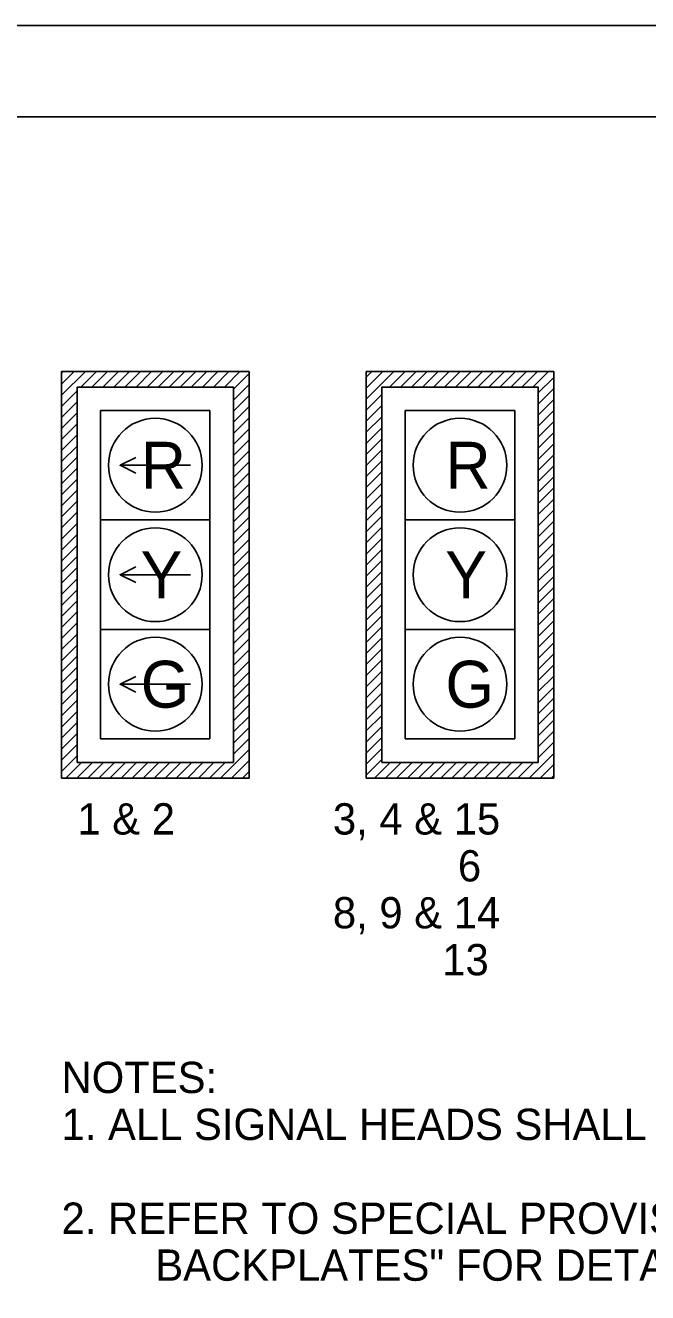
# Model space of a CAD drawing. Extents: x 1710114 to 1711114, y 557211 to 557851.
# Drawn here: x 1710304.6 to 1710384.3, y 557689.1 to 557851.1 of the extents above; entities that cross this region are included whole.
import ezdxf

# ---------------------------------------------------------------- set-up
doc = ezdxf.new("R2010")
doc.units = 0
for name, color, linetype in [('E_Existing ROW', 7, 'Continuous'), ('R_Alt Surface', 7, 'Continuous'), ('R_Alt Surface Annot', 7, 'Continuous'), ('R_Dimension', 7, 'Continuous')]:
    doc.layers.add(name, color=color, linetype=linetype)

msp = doc.modelspace()

# ---------------------------------------------------------------- linework, layer by layer
at = {"layer": 'E_Existing ROW'}
for p, q in [((1710309.23, 557806.9), (1710333.23, 557806.9)), ((1710309.23, 557754.9), (1710309.23, 557806.9)), ((1710309.23, 557803.85), (1710312.28, 557806.9)), ((1710309.23, 557805.26), (1710310.86, 557806.9)), ((1710309.23, 557806.68), (1710309.45, 557806.9)), ((1710311.69, 557804.9), (1710313.69, 557806.9)), ((1710313.1, 557804.9), (1710315.1, 557806.9)), ((1710314.52, 557804.9), (1710316.52, 557806.9)), ((1710315.93, 557804.9), (1710317.93, 557806.9)), ((1710317.35, 557804.9), (1710319.35, 557806.9)), ((1710318.76, 557804.9), (1710320.76, 557806.9)), ((1710320.18, 557804.9), (1710322.18, 557806.9)), ((1710321.59, 557804.9), (1710323.59, 557806.9)), ((1710323, 557804.9), (1710325, 557806.9)), ((1710324.42, 557804.9), (1710326.42, 557806.9)), ((1710325.83, 557804.9), (1710327.83, 557806.9)), ((1710327.25, 557804.9), (1710329.25, 557806.9)), ((1710328.66, 557804.9), (1710330.66, 557806.9)), ((1710330.07, 557804.9), (1710332.07, 557806.9)), ((1710331.23, 557804.63), (1710333.23, 557806.63)), ((1710333.23, 557806.9), (1710333.23, 557754.9)), ((1710372.23, 557806.9), (1710348.23, 557806.9)), ((1710348.23, 557806.9), (1710348.23, 557754.9)), ((1710348.23, 557803.35), (1710351.77, 557806.9)), ((1710348.23, 557804.76), (1710350.36, 557806.9)), ((1710348.23, 557806.18), (1710348.94, 557806.9)), ((1710351.19, 557804.9), (1710353.19, 557806.9)), ((1710352.6, 557804.9), (1710354.6, 557806.9)), ((1710354.02, 557804.9), (1710356.02, 557806.9)), ((1710355.43, 557804.9), (1710357.43, 557806.9)), ((1710356.84, 557804.9), (1710358.84, 557806.9)), ((1710358.26, 557804.9), (1710360.26, 557806.9)), ((1710359.67, 557804.9), (1710361.67, 557806.9)), ((1710361.09, 557804.9), (1710363.09, 557806.9)), ((1710362.5, 557804.9), (1710364.5, 557806.9)), ((1710363.91, 557804.9), (1710365.91, 557806.9)), ((1710365.33, 557804.9), (1710367.33, 557806.9)), ((1710366.74, 557804.9), (1710368.74, 557806.9)), ((1710368.16, 557804.9), (1710370.16, 557806.9)), ((1710369.57, 557804.9), (1710371.57, 557806.9)), ((1710372.23, 557754.9), (1710372.23, 557806.9)), ((1710331.23, 557803.22), (1710333.23, 557805.22)), ((1710370.23, 557804.14), (1710372.23, 557806.14)), ((1710309.23, 557802.43), (1710311.23, 557804.43)), ((1710331.23, 557801.81), (1710333.23, 557803.81)), ((1710348.23, 557801.94), (1710350.23, 557803.94)), ((1710370.23, 557802.72), (1710372.23, 557804.72)), ((1710370.23, 557801.31), (1710372.23, 557803.31)), ((1710309.23, 557801.02), (1710311.23, 557803.02)), ((1710309.23, 557799.6), (1710311.23, 557801.6)), ((1710314.23, 557801.9), (1710328.23, 557801.9)), ((1710314.23, 557801.9), (1710314.23, 557787.9)), ((1710328.23, 557801.9), (1710328.23, 557787.9)), ((1710331.23, 557800.39), (1710333.23, 557802.39)), ((1710348.23, 557800.52), (1710350.23, 557802.52)), ((1710353.23, 557801.9), (1710367.23, 557801.9)), ((1710353.23, 557801.9), (1710353.23, 557787.9)), ((1710367.23, 557801.9), (1710367.23, 557787.9)), ((1710370.23, 557799.89), (1710372.23, 557801.89)), ((1710309.23, 557798.19), (1710311.23, 557800.19)), ((1710331.23, 557798.98), (1710333.23, 557800.98)), ((1710348.23, 557799.11), (1710350.23, 557801.11)), ((1710370.23, 557798.48), (1710372.23, 557800.48)), ((1710309.23, 557796.78), (1710311.23, 557798.78)), ((1710331.23, 557797.56), (1710333.23, 557799.56)), ((1710348.23, 557797.69), (1710350.23, 557799.69)), ((1710348.23, 557796.28), (1710350.23, 557798.28)), ((1710370.23, 557797.07), (1710372.23, 557799.07)), ((1710309.23, 557795.36), (1710311.23, 557797.36)), ((1710331.23, 557796.15), (1710333.23, 557798.15)), ((1710331.23, 557794.73), (1710333.23, 557796.73)), ((1710348.23, 557794.87), (1710350.23, 557796.87)), ((1710370.23, 557795.65), (1710372.23, 557797.65)), ((1710309.23, 557793.95), (1710311.23, 557795.95)), ((1710331.23, 557793.32), (1710333.23, 557795.32)), ((1710348.23, 557793.45), (1710350.23, 557795.45)), ((1710370.23, 557794.24), (1710372.23, 557796.24)), ((1710309.23, 557792.53), (1710311.23, 557794.53)), ((1710325.73, 557794.9), (1710316.73, 557794.9)), ((1710331.23, 557791.91), (1710333.23, 557793.91)), ((1710348.23, 557792.04), (1710350.23, 557794.04)), ((1710370.23, 557792.82), (1710372.23, 557794.82)), ((1710370.23, 557791.41), (1710372.23, 557793.41)), ((1710309.23, 557791.12), (1710311.23, 557793.12)), ((1710331.23, 557790.49), (1710333.23, 557792.49)), ((1710348.23, 557790.62), (1710350.23, 557792.62)), ((1710370.23, 557790), (1710372.23, 557792)), ((1710309.23, 557789.71), (1710311.23, 557791.71)), ((1710309.23, 557788.29), (1710311.23, 557790.29)), ((1710331.23, 557789.08), (1710333.23, 557791.08)), ((1710348.23, 557789.21), (1710350.23, 557791.21)), ((1710370.23, 557788.58), (1710372.23, 557790.58)), ((1710309.23, 557786.88), (1710311.23, 557788.88)), ((1710331.23, 557787.66), (1710333.23, 557789.66)), ((1710348.23, 557787.79), (1710350.23, 557789.79)), ((1710370.23, 557787.17), (1710372.23, 557789.17)), ((1710309.23, 557785.46), (1710311.23, 557787.46)), ((1710314.23, 557787.9), (1710328.23, 557787.9)), ((1710314.23, 557787.9), (1710314.23, 557773.9)), ((1710328.23, 557787.9), (1710328.23, 557773.9)), ((1710331.23, 557786.25), (1710333.23, 557788.25)), ((1710348.23, 557786.38), (1710350.23, 557788.38)), ((1710348.23, 557784.97), (1710350.23, 557786.97)), ((1710353.23, 557787.9), (1710367.23, 557787.9)), ((1710353.23, 557787.9), (1710353.23, 557773.9)), ((1710367.23, 557787.9), (1710367.23, 557773.9)), ((1710370.23, 557785.75), (1710372.23, 557787.75)), ((1710309.23, 557784.05), (1710311.23, 557786.05)), ((1710331.23, 557784.84), (1710333.23, 557786.84)), ((1710331.23, 557783.42), (1710333.23, 557785.42)), ((1710348.23, 557783.55), (1710350.23, 557785.55)), ((1710370.23, 557784.34), (1710372.23, 557786.34)), ((1710309.23, 557782.63), (1710311.23, 557784.63)), ((1710331.23, 557782.01), (1710333.23, 557784.01)), ((1710348.23, 557782.14), (1710350.23, 557784.14)), ((1710370.23, 557782.92), (1710372.23, 557784.92)), ((1710309.23, 557781.22), (1710311.23, 557783.22)), ((1710331.23, 557780.59), (1710333.23, 557782.59)), ((1710348.23, 557780.72), (1710350.23, 557782.72)), ((1710370.23, 557781.51), (1710372.23, 557783.51)), ((1710370.23, 557780.1), (1710372.23, 557782.1)), ((1710309.23, 557779.81), (1710311.23, 557781.81)), ((1710325.73, 557780.9), (1710316.73, 557780.9)), ((1710331.23, 557779.18), (1710333.23, 557781.18)), ((1710348.23, 557779.31), (1710350.23, 557781.31)), ((1710370.23, 557778.68), (1710372.23, 557780.68)), ((1710309.23, 557778.39), (1710311.23, 557780.39)), ((1710309.23, 557776.98), (1710311.23, 557778.98)), ((1710331.23, 557777.76), (1710333.23, 557779.76)), ((1710348.23, 557777.89), (1710350.23, 557779.89)), ((1710370.23, 557777.27), (1710372.23, 557779.27)), ((1710309.23, 557775.56), (1710311.23, 557777.56)), ((1710331.23, 557776.35), (1710333.23, 557778.35)), ((1710348.23, 557776.48), (1710350.23, 557778.48)), ((1710370.23, 557775.85), (1710372.23, 557777.85)), ((1710309.23, 557774.15), (1710311.23, 557776.15)), ((1710331.23, 557774.94), (1710333.23, 557776.94)), ((1710348.23, 557775.07), (1710350.23, 557777.07)), ((1710348.23, 557773.65), (1710350.23, 557775.65)), ((1710370.23, 557774.44), (1710372.23, 557776.44)), ((1710309.23, 557772.73), (1710311.23, 557774.73)), ((1710331.23, 557773.52), (1710333.23, 557775.52)), ((1710331.23, 557772.11), (1710333.23, 557774.11)), ((1710348.23, 557772.24), (1710350.23, 557774.24)), ((1710370.23, 557773.02), (1710372.23, 557775.02)), ((1710309.23, 557771.32), (1710311.23, 557773.32)), ((1710314.23, 557773.9), (1710328.23, 557773.9)), ((1710314.23, 557773.9), (1710314.23, 557759.9)), ((1710328.23, 557773.9), (1710328.23, 557759.9)), ((1710331.23, 557770.69), (1710333.23, 557772.69)), ((1710348.23, 557770.82), (1710350.23, 557772.82)), ((1710353.23, 557773.9), (1710367.23, 557773.9)), ((1710353.23, 557773.9), (1710353.23, 557759.9)), ((1710367.23, 557773.9), (1710367.23, 557759.9)), ((1710370.23, 557771.61), (1710372.23, 557773.61)), ((1710309.23, 557769.91), (1710311.23, 557771.91)), ((1710331.23, 557769.28), (1710333.23, 557771.28)), ((1710348.23, 557769.41), (1710350.23, 557771.41)), ((1710370.23, 557770.2), (1710372.23, 557772.2)), ((1710370.23, 557768.78), (1710372.23, 557770.78)), ((1710309.23, 557768.49), (1710311.23, 557770.49)), ((1710331.23, 557767.86), (1710333.23, 557769.86)), ((1710348.23, 557768), (1710350.23, 557770)), ((1710370.23, 557767.37), (1710372.23, 557769.37)), ((1710309.23, 557767.08), (1710311.23, 557769.08)), ((1710309.23, 557765.66), (1710311.23, 557767.66)), ((1710331.23, 557766.45), (1710333.23, 557768.45)), ((1710348.23, 557766.58), (1710350.23, 557768.58)), ((1710370.23, 557765.95), (1710372.23, 557767.95)), ((1710309.23, 557764.25), (1710311.23, 557766.25)), ((1710325.73, 557766.9), (1710316.73, 557766.9)), ((1710331.23, 557765.04), (1710333.23, 557767.04)), ((1710348.23, 557765.17), (1710350.23, 557767.17)), ((1710370.23, 557764.54), (1710372.23, 557766.54)), ((1710309.23, 557762.84), (1710311.23, 557764.84)), ((1710331.23, 557763.62), (1710333.23, 557765.62)), ((1710348.23, 557763.75), (1710350.23, 557765.75)), ((1710348.23, 557762.34), (1710350.23, 557764.34)), ((1710370.23, 557763.13), (1710372.23, 557765.13)), ((1710309.23, 557761.42), (1710311.23, 557763.42)), ((1710331.23, 557762.21), (1710333.23, 557764.21)), ((1710331.23, 557760.79), (1710333.23, 557762.79)), ((1710348.23, 557760.92), (1710350.23, 557762.92)), ((1710370.23, 557761.71), (1710372.23, 557763.71)), ((1710309.23, 557760.01), (1710311.23, 557762.01)), ((1710331.23, 557759.38), (1710333.23, 557761.38)), ((1710348.23, 557759.51), (1710350.23, 557761.51)), ((1710370.23, 557760.3), (1710372.23, 557762.3)), ((1710309.23, 557758.59), (1710311.23, 557760.59)), ((1710314.23, 557759.9), (1710328.23, 557759.9)), ((1710331.23, 557757.97), (1710333.23, 557759.97)), ((1710348.23, 557758.1), (1710350.23, 557760.1)), ((1710353.23, 557759.9), (1710367.23, 557759.9)), ((1710370.23, 557758.88), (1710372.23, 557760.88)), ((1710370.23, 557757.47), (1710372.23, 557759.47)), ((1710309.23, 557757.18), (1710311.23, 557759.18)), ((1710309.23, 557755.76), (1710311.23, 557757.76)), ((1710329.57, 557754.9), (1710333.23, 557758.55)), ((1710348.23, 557756.68), (1710350.23, 557758.68)), ((1710369.07, 557754.9), (1710372.23, 557758.05)), ((1710309.77, 557754.9), (1710311.77, 557756.9)), ((1710311.19, 557754.9), (1710313.19, 557756.9)), ((1710312.6, 557754.9), (1710314.6, 557756.9)), ((1710314.02, 557754.9), (1710316.02, 557756.9)), ((1710315.43, 557754.9), (1710317.43, 557756.9)), ((1710316.84, 557754.9), (1710318.84, 557756.9)), ((1710318.26, 557754.9), (1710320.26, 557756.9)), ((1710319.67, 557754.9), (1710321.67, 557756.9)), ((1710321.09, 557754.9), (1710323.09, 557756.9)), ((1710322.5, 557754.9), (1710324.5, 557756.9)), ((1710323.92, 557754.9), (1710325.92, 557756.9)), ((1710325.33, 557754.9), (1710327.33, 557756.9)), ((1710326.74, 557754.9), (1710328.74, 557756.9)), ((1710328.16, 557754.9), (1710330.16, 557756.9)), ((1710330.99, 557754.9), (1710333.23, 557757.14)), ((1710348.23, 557755.27), (1710350.23, 557757.27)), ((1710349.27, 557754.9), (1710351.27, 557756.9)), ((1710350.68, 557754.9), (1710352.68, 557756.9)), ((1710352.1, 557754.9), (1710354.1, 557756.9)), ((1710353.51, 557754.9), (1710355.51, 557756.9)), ((1710354.93, 557754.9), (1710356.93, 557756.9)), ((1710356.34, 557754.9), (1710358.34, 557756.9)), ((1710357.76, 557754.9), (1710359.76, 557756.9)), ((1710359.17, 557754.9), (1710361.17, 557756.9)), ((1710360.58, 557754.9), (1710362.58, 557756.9)), ((1710362, 557754.9), (1710364, 557756.9)), ((1710363.41, 557754.9), (1710365.41, 557756.9)), ((1710364.83, 557754.9), (1710366.83, 557756.9)), ((1710366.24, 557754.9), (1710368.24, 557756.9)), ((1710367.65, 557754.9), (1710369.65, 557756.9)), ((1710370.48, 557754.9), (1710372.23, 557756.64)), ((1710333.23, 557754.9), (1710309.23, 557754.9)), ((1710332.4, 557754.9), (1710333.23, 557755.72)), ((1710348.23, 557754.9), (1710372.23, 557754.9)), ((1710371.9, 557754.9), (1710372.23, 557755.23))]:
    msp.add_line(p, q, dxfattribs=at)
for points in [[(1710311.23, 557804.9), (1710331.23, 557804.9), (1710331.23, 557756.9), (1710311.23, 557756.9)], [(1710370.23, 557756.9), (1710370.23, 557804.9), (1710350.23, 557804.9), (1710350.23, 557756.9)]]:
    msp.add_lwpolyline(points, close=True, dxfattribs=at)
for points in [[(1710318.73, 557795.9), (1710316.73, 557794.9), (1710318.73, 557793.9)], [(1710318.73, 557781.9), (1710316.73, 557780.9), (1710318.73, 557779.9)], [(1710318.73, 557767.9), (1710316.73, 557766.9), (1710318.73, 557765.9)]]:
    msp.add_lwpolyline(points, dxfattribs=at)
for centre in [(1710321.23, 557794.9), (1710360.23, 557794.9), (1710321.23, 557780.9), (1710360.23, 557780.9), (1710321.23, 557766.9), (1710360.23, 557766.9)]:
    msp.add_circle(centre, 6, dxfattribs=at)
at = {"layer": 'R_Alt Surface'}
msp.add_line((1710151.54, 557839.47), (1711100.08, 557839.47), dxfattribs=at)
at = {"layer": 'R_Alt Surface Annot'}
msp.add_line((1710114.34, 557851.15), (1711114.34, 557851.15), dxfattribs=at)
msp.add_lwpolyline([(1710114.32, 557851.15), (1711114.34, 557851.15), (1711114.34, 557211.14), (1710114.32, 557211.14)], close=True, dxfattribs=at)

# ---------------------------------------------------------------- texts
at = {"layer": 'E_Existing ROW'}
for s, p in [('R', (1710319.36, 557791.9)), ('R', (1710358.36, 557791.9)), ('Y', (1710319.34, 557777.9)), ('Y', (1710358.34, 557777.9)), ('G', (1710319.36, 557763.9)), ('G', (1710358.36, 557763.9))]:
    msp.add_text(s, height=6, dxfattribs=at).set_placement(p)
at = {"layer": 'R_Dimension'}
for s, p in [('1 & 2', (1710311.26, 557747.68)), ('3, 4 & 15', (1710343.96, 557747.68)), ('6', (1710359.96, 557741.68)), ('8, 9 & 14', (1710343.96, 557735.68)), ('13', (1710357.96, 557729.68)), ('NOTES:', (1710309.23, 557714.62)), ('1. ALL SIGNAL HEADS SHALL HAVE BACKPLATES.', (1710309.23, 557708.62)), ('2. REFER TO SPECIAL PROVISION "RETROREFLECTIVE', (1710309.23, 557696.62)), ('BACKPLATES" FOR DETAILS ON REQUIREMENTS FOR ', (1710321.23, 557690.62))]:
    msp.add_text(s, height=4, dxfattribs=at).set_placement(p)

doc.saveas('drawing.dxf')
